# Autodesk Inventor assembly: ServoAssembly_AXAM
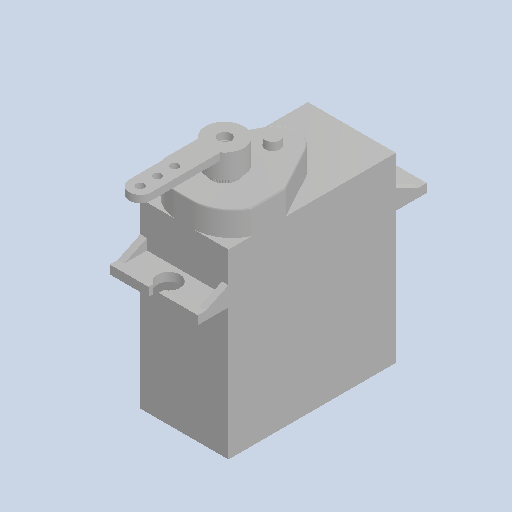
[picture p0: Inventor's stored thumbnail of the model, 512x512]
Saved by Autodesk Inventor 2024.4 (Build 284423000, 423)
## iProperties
Created: 2025-06
Part Number: ServoAssembly_AXAM
Document SubType Name: Assembly
Designer: AdminForWorker
Title: ServoAssembly_AXAM v1
Author: AdminForWorker
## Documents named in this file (3)
- c:\worker\convert-fusion-r02-cosv3\tmp\job-1\29\temp\files\88337bce-659a-4bbe-ab04-221f2da505fe\4e46a4e1-fea3-450c-b6b7-ddb3ecfd538d.iam
- c:\worker\convert-fusion-r02-cosv3\tmp\job-1\29\temp\files\88337bce-659a-4bbe-ab04-221f2da505fe\ServoCoupling v2.ipt
- c:\worker\convert-fusion-r02-cosv3\tmp\job-1\29\temp\files\88337bce-659a-4bbe-ab04-221f2da505fe\Part4.ipt
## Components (2 placed, 2 different names)
1. ServoCoupling v2:1
2. Part4
